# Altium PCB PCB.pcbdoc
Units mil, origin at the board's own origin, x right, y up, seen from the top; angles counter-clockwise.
Board outline 2756 x 2755.7 mil, 2 copper layers (Top Layer, Bottom Layer), stack 62.2 mil thick; 25 components, 17 nets, 72 pads, 16 vias.
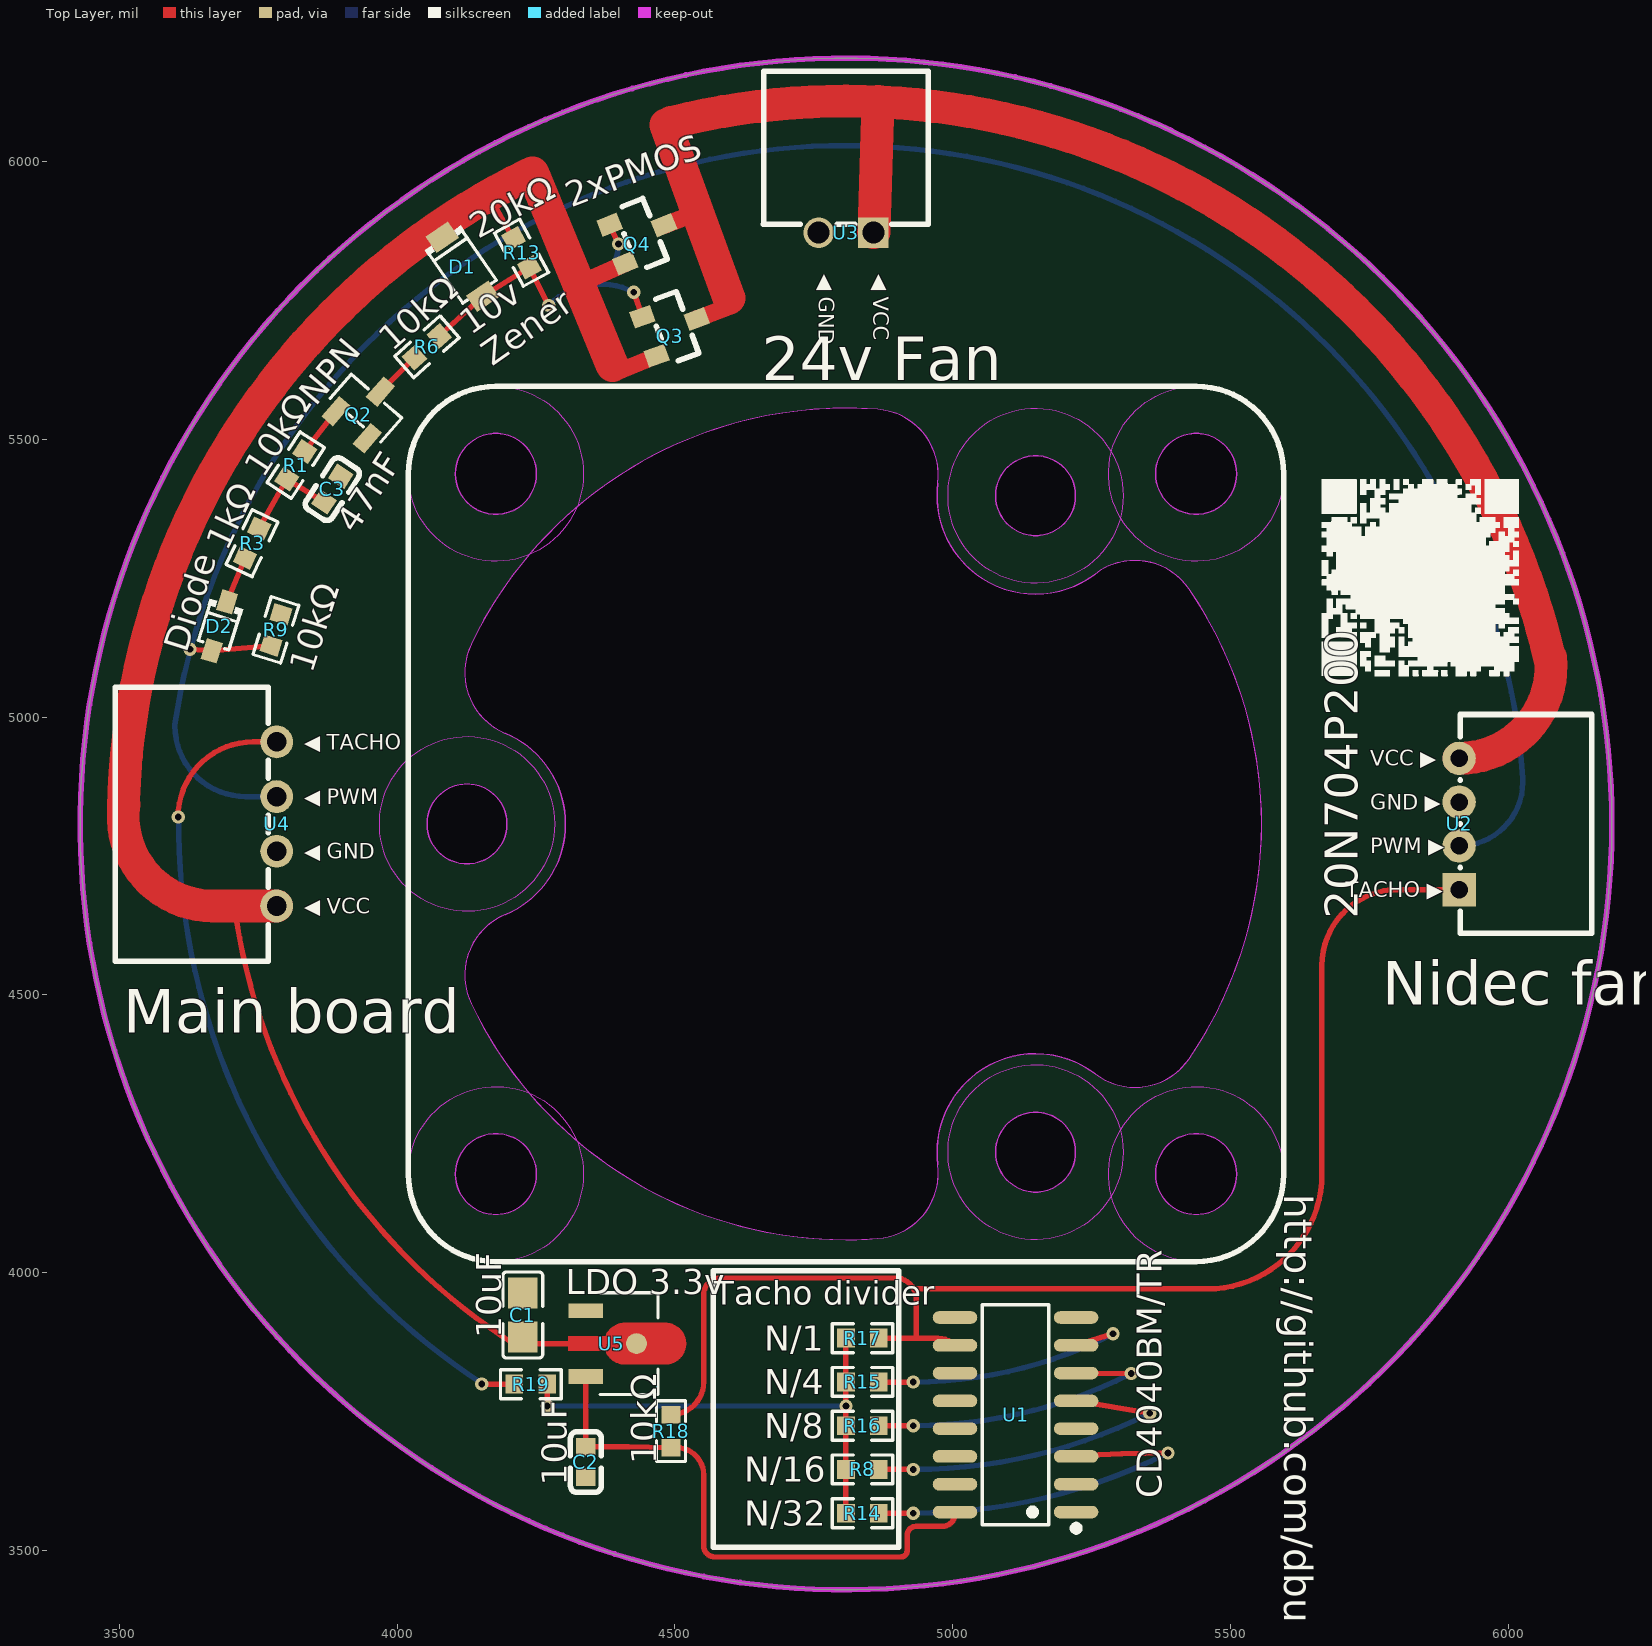
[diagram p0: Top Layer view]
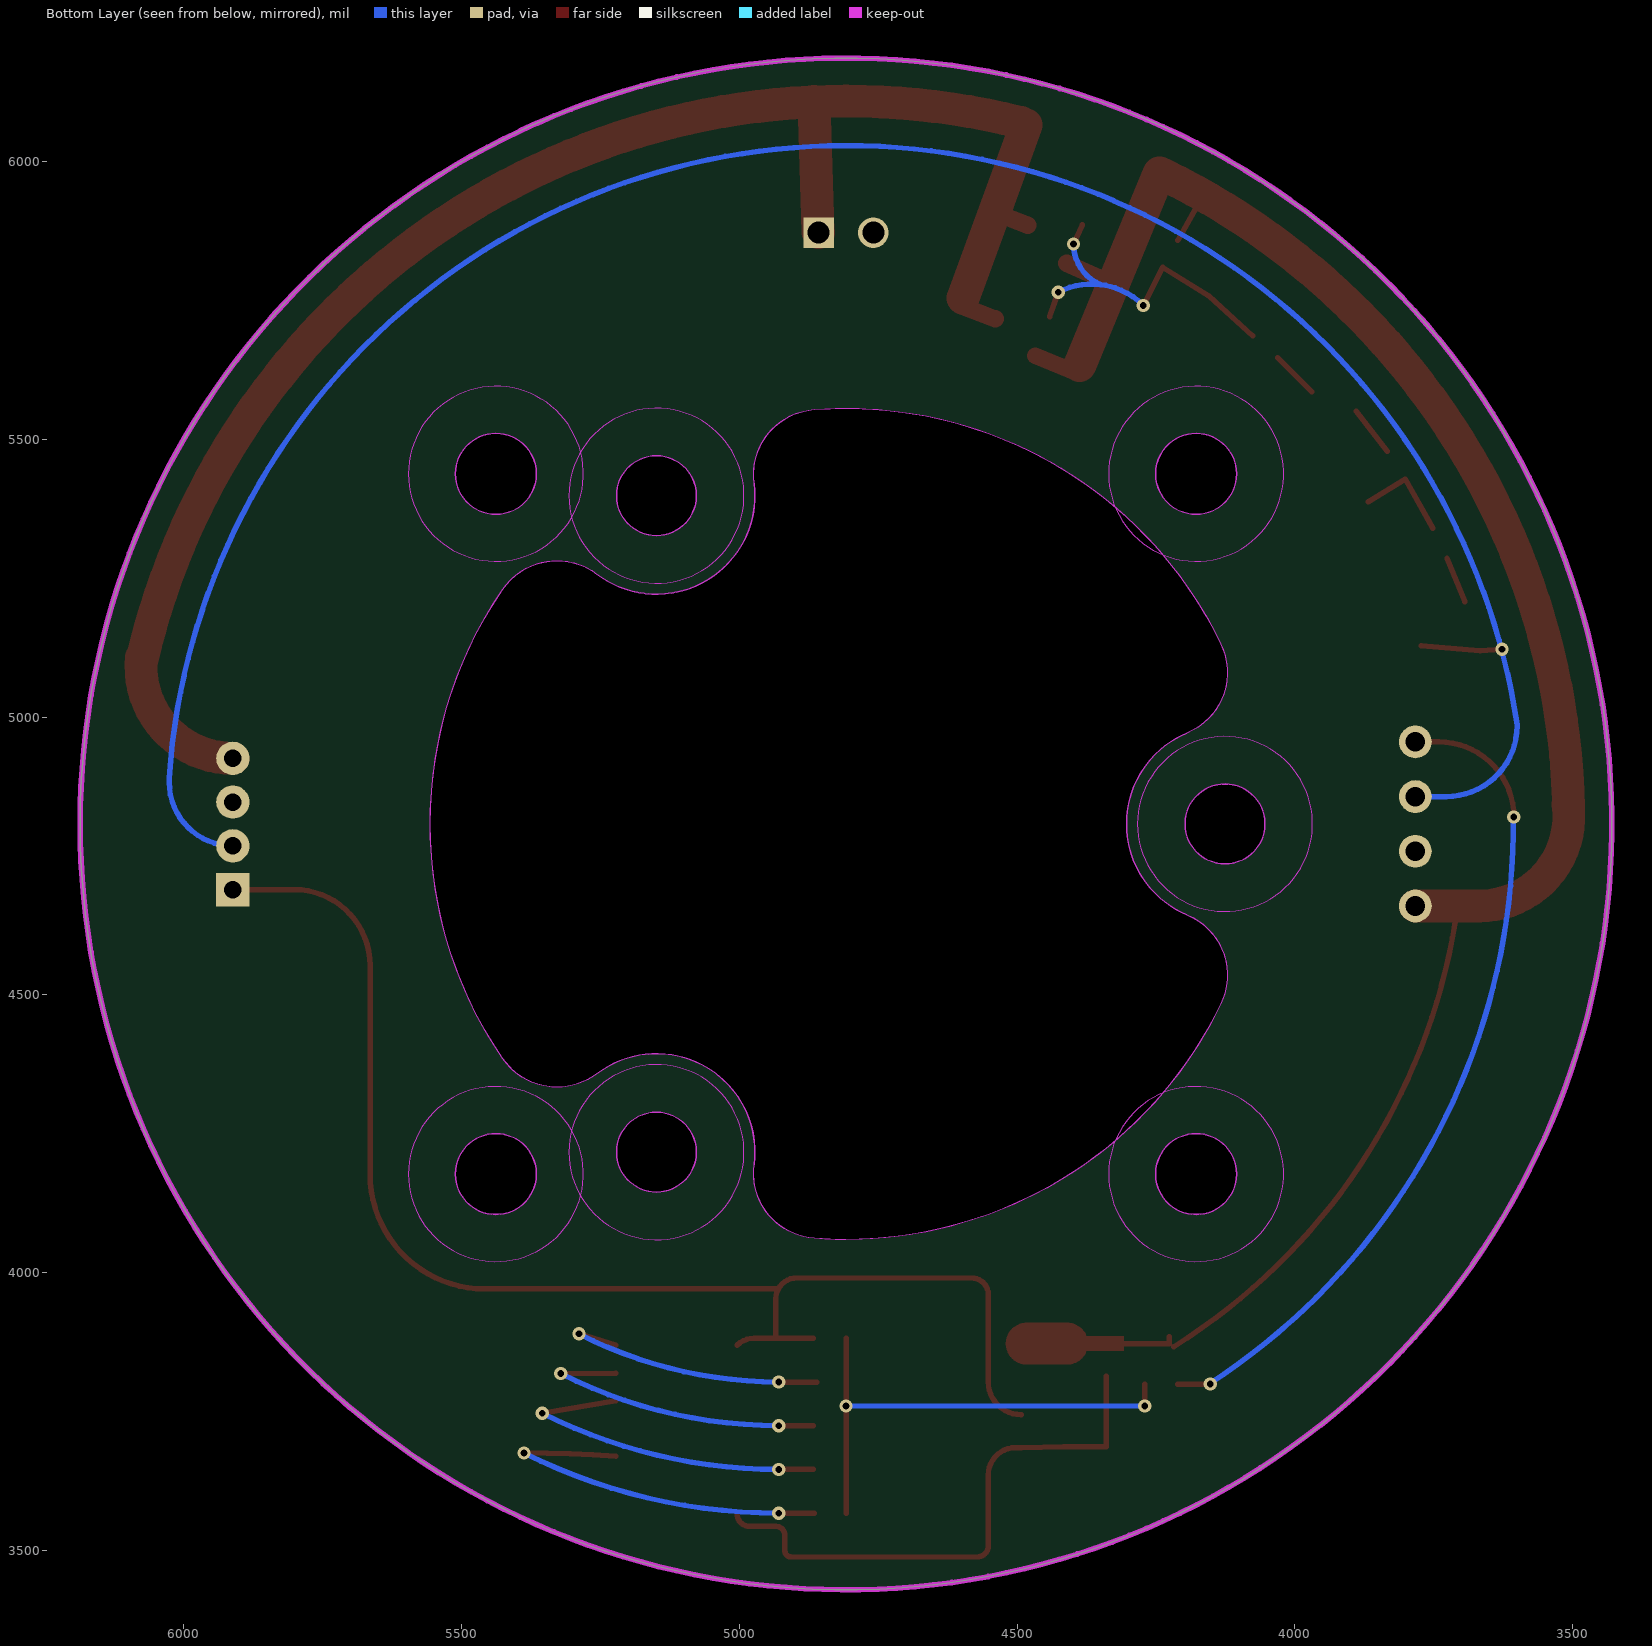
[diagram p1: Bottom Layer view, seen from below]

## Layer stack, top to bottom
Top Solder Mask Layer: solder mask 0.4, Dk 3.3
Top Layer: signal copper 1.4
Dielectric1: surface 59.4, FR4, Dk 4.5
Bottom Layer: signal copper 1.4
Bottom Solder Mask Layer: solder mask 0.4, Dk 3.3

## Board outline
6185.7,4807.7 ccw(c4807.7,4807.7) 3429.8,4807.7 ccw(c4807.7,4807.7)
cut-out: 348 vertices, not listed, extent 4121.7,4059.7 5555.7,5555.7
cut-out: 5364.7,5437.6 5365.1,5445.3 5366.3,5452.8 5368.3,5460.2 5371,5467.3 5374.5,5474.1 5378.6,5480.5 5383.4,5486.4 5388.8,5491.8 5394.8,5496.6 5401.2,5500.8 5408,5504.2 5415.1,5507 5422.5,5508.9 5430,5510.1 5437.6,5510.5 5445.3,5510.1 5452.8,5508.9 5460.2,5507 5467.3,5504.2 5474.1,5500.8 5480.5,5496.6 5486.4,5491.8 5491.8,5486.4 5496.6,5480.5 5500.8,5474.1 5504.2,5467.3 5507,5460.2 5508.9,5452.8 5510.1,5445.3 5510.5,5437.6 5510.1,5430 5508.9,5422.5 5507,5415.1 5504.2,5408 5500.8,5401.2 5496.6,5394.8 5491.8,5388.8 5486.4,5383.4 5480.5,5378.6 5474.1,5374.5 5467.3,5371 5460.2,5368.3 5452.8,5366.3 5445.3,5365.1 5437.6,5364.7 5430,5365.1 5422.5,5366.3 5415.1,5368.3 5408,5371 5401.2,5374.5 5394.8,5378.6 5388.8,5383.4 5383.4,5388.8 5378.6,5394.8 5374.5,5401.2 5371,5408 5368.3,5415.1 5366.3,5422.5 5365.1,5430
cut-out: 5364.7,4177.8 5365.1,4185.4 5366.3,4192.9 5368.3,4200.3 5371,4207.4 5374.5,4214.2 5378.6,4220.6 5383.4,4226.6 5388.8,4232 5394.8,4236.8 5401.2,4240.9 5408,4244.4 5415.1,4247.1 5422.5,4249.1 5430,4250.3 5437.6,4250.7 5445.3,4250.3 5452.8,4249.1 5460.2,4247.1 5467.3,4244.4 5474.1,4240.9 5480.5,4236.8 5486.4,4232 5491.8,4226.6 5496.6,4220.6 5500.8,4214.2 5504.2,4207.4 5507,4200.3 5508.9,4192.9 5510.1,4185.4 5510.5,4177.8 5510.1,4170.2 5508.9,4162.6 5507,4155.3 5504.2,4148.1 5500.8,4141.3 5496.6,4134.9 5491.8,4129 5486.4,4123.6 5480.5,4118.8 5474.1,4114.6 5467.3,4111.2 5460.2,4108.4 5452.8,4106.5 5445.3,4105.3 5437.6,4104.9 5430,4105.3 5422.5,4106.5 5415.1,4108.4 5408,4111.2 5401.2,4114.6 5394.8,4118.8 5388.8,4123.6 5383.4,4129 5378.6,4134.9 5374.5,4141.3 5371,4148.1 5368.3,4155.3 5366.3,4162.6 5365.1,4170.2
cut-out: 5076.7,4217.2 5077.1,4224.7 5078.3,4232.1 5080.3,4239.4 5083,4246.4 5086.4,4253.1 5090.5,4259.4 5095.2,4265.3 5100.5,4270.6 5106.4,4275.4 5112.7,4279.5 5119.4,4282.9 5126.4,4285.6 5133.7,4287.5 5141.1,4288.7 5148.7,4289.1 5156.2,4288.7 5163.6,4287.5 5170.9,4285.6 5177.9,4282.9 5184.6,4279.5 5190.9,4275.4 5196.8,4270.6 5202.1,4265.3 5206.9,4259.4 5211,4253.1 5214.4,4246.4 5217.1,4239.4 5219,4232.1 5220.2,4224.7 5220.6,4217.2 5220.2,4209.6 5219,4202.2 5217.1,4194.9 5214.4,4187.9 5211,4181.2 5206.9,4174.9 5202.1,4169 5196.8,4163.7 5190.9,4159 5184.6,4154.9 5177.9,4151.4 5170.9,4148.8 5163.6,4146.8 5156.2,4145.6 5148.7,4145.2 5141.1,4145.6 5133.7,4146.8 5126.4,4148.8 5119.4,4151.4 5112.7,4154.9 5106.4,4159 5100.5,4163.7 5095.2,4169 5090.5,4174.9 5086.4,4181.2 5083,4187.9 5080.3,4194.9 5078.3,4202.2 5077.1,4209.6
cut-out: 5076.7,5398.3 5077.1,5405.8 5078.3,5413.2 5080.3,5420.5 5083,5427.5 5086.4,5434.2 5090.5,5440.5 5095.2,5446.4 5100.5,5451.7 5106.4,5456.5 5112.7,5460.6 5119.4,5464 5126.4,5466.7 5133.7,5468.6 5141.1,5469.8 5148.7,5470.2 5156.2,5469.8 5163.6,5468.6 5170.9,5466.7 5177.9,5464 5184.6,5460.6 5190.9,5456.5 5196.8,5451.7 5202.1,5446.4 5206.9,5440.5 5211,5434.2 5214.4,5427.5 5217.1,5420.5 5219,5413.2 5220.2,5405.8 5220.6,5398.3 5220.2,5390.7 5219,5383.3 5217.1,5376 5214.4,5369 5211,5362.3 5206.9,5356 5202.1,5350.1 5196.8,5344.8 5190.9,5340.1 5184.6,5336 5177.9,5332.5 5170.9,5329.9 5163.6,5327.9 5156.2,5326.7 5148.7,5326.3 5141.1,5326.7 5133.7,5327.9 5126.4,5329.9 5119.4,5332.5 5112.7,5336 5106.4,5340.1 5100.5,5344.8 5095.2,5350.1 5090.5,5356 5086.4,5362.3 5083,5369 5080.3,5376 5078.3,5383.3 5077.1,5390.7
cut-out: 4104.9,5437.6 4105.3,5445.3 4106.5,5452.8 4108.4,5460.2 4111.2,5467.3 4114.6,5474.1 4118.8,5480.5 4123.6,5486.4 4129,5491.8 4134.9,5496.6 4141.3,5500.8 4148.1,5504.2 4155.3,5507 4162.6,5508.9 4170.2,5510.1 4177.8,5510.5 4185.4,5510.1 4192.9,5508.9 4200.3,5507 4207.4,5504.2 4214.2,5500.8 4220.6,5496.6 4226.6,5491.8 4232,5486.4 4236.8,5480.5 4240.9,5474.1 4244.4,5467.3 4247.1,5460.2 4249.1,5452.8 4250.3,5445.3 4250.7,5437.6 4250.3,5430 4249.1,5422.5 4247.1,5415.1 4244.4,5408 4240.9,5401.2 4236.8,5394.8 4232,5388.8 4226.6,5383.4 4220.6,5378.6 4214.2,5374.5 4207.4,5371 4200.3,5368.3 4192.9,5366.3 4185.4,5365.1 4177.8,5364.7 4170.2,5365.1 4162.6,5366.3 4155.3,5368.3 4148.1,5371 4141.3,5374.5 4134.9,5378.6 4129,5383.4 4123.6,5388.8 4118.8,5394.8 4114.6,5401.2 4111.2,5408 4108.4,5415.1 4106.5,5422.5 4105.3,5430
cut-out: 4053.9,4807.7 4054.3,4815.2 4055.4,4822.7 4057.4,4829.9 4060.1,4837 4063.5,4843.7 4067.6,4850 4072.3,4855.8 4077.7,4861.2 4083.5,4865.9 4089.8,4870 4096.5,4873.4 4103.6,4876.1 4110.8,4878.1 4118.3,4879.2 4125.8,4879.6 4133.3,4879.2 4140.8,4878.1 4148,4876.1 4155.1,4873.4 4161.8,4870 4168.1,4865.9 4173.9,4861.2 4179.3,4855.8 4184,4850 4188.1,4843.7 4191.5,4837 4194.2,4829.9 4196.2,4822.7 4197.3,4815.2 4197.7,4807.7 4197.3,4800.2 4196.2,4792.8 4194.2,4785.5 4191.5,4778.5 4188.1,4771.7 4184,4765.4 4179.3,4759.6 4173.9,4754.3 4168.1,4749.5 4161.8,4745.4 4155.1,4742 4148,4739.3 4140.8,4737.4 4133.3,4736.2 4125.8,4735.8 4118.3,4736.2 4110.8,4737.4 4103.6,4739.3 4096.5,4742 4089.8,4745.4 4083.5,4749.5 4077.7,4754.3 4072.3,4759.6 4067.6,4765.4 4063.5,4771.7 4060.1,4778.5 4057.4,4785.5 4055.4,4792.8 4054.3,4800.2
cut-out: 4104.9,4177.8 4105.3,4185.4 4106.5,4192.9 4108.4,4200.3 4111.2,4207.4 4114.6,4214.2 4118.8,4220.6 4123.6,4226.6 4129,4232 4134.9,4236.8 4141.3,4240.9 4148.1,4244.4 4155.3,4247.1 4162.6,4249.1 4170.2,4250.3 4177.8,4250.7 4185.4,4250.3 4192.9,4249.1 4200.3,4247.1 4207.4,4244.4 4214.2,4240.9 4220.6,4236.8 4226.6,4232 4232,4226.6 4236.8,4220.6 4240.9,4214.2 4244.4,4207.4 4247.1,4200.3 4249.1,4192.9 4250.3,4185.4 4250.7,4177.8 4250.3,4170.2 4249.1,4162.6 4247.1,4155.3 4244.4,4148.1 4240.9,4141.3 4236.8,4134.9 4232,4129 4226.6,4123.6 4220.6,4118.8 4214.2,4114.6 4207.4,4111.2 4200.3,4108.4 4192.9,4106.5 4185.4,4105.3 4177.8,4104.9 4170.2,4105.3 4162.6,4106.5 4155.3,4108.4 4148.1,4111.2 4141.3,4114.6 4134.9,4118.8 4129,4123.6 4123.6,4129 4118.8,4134.9 4114.6,4141.3 4111.2,4148.1 4108.4,4155.3 4106.5,4162.6 4105.3,4170.2

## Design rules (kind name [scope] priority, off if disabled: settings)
BoardOutlineClearance safeClearance [All] p0: genericclearance=10 ignorepadtopadclearanceinfootprint=FALSE except(0: Arc-SplitContinuation Track-SplitContinuation SMDPad-SplitContinuation THPad-SplitContinuation Via-SplitContinuation Fill-SplitContinuation Poly-SplitContinuation Region-SplitContinuation Text-SplitContinuation)
BoardOutlineClearance Plane_innerPlane [All] p0: genericclearance=10 ignorepadtopadclearanceinfootprint=FALSE except(0: Arc-SplitContinuation Track-SplitContinuation SMDPad-SplitContinuation THPad-SplitContinuation Via-SplitContinuation Fill-SplitContinuation Poly-SplitContinuation Region-SplitContinuation Text-SplitContinuation)
BoardOutlineClearance Copper_copperRegion [All] p0: genericclearance=10 ignorepadtopadclearanceinfootprint=FALSE except(0: Arc-SplitContinuation Track-SplitContinuation SMDPad-SplitContinuation THPad-SplitContinuation Via-SplitContinuation Fill-SplitContinuation Poly-SplitContinuation Region-SplitContinuation Text-SplitContinuation)
BoardOutlineClearance thick [All] p0: genericclearance=10 ignorepadtopadclearanceinfootprint=FALSE except(0: Arc-SplitContinuation Track-SplitContinuation SMDPad-SplitContinuation THPad-SplitContinuation Via-SplitContinuation Fill-SplitContinuation Poly-SplitContinuation Region-SplitContinuation Text-SplitContinuation)
BoardOutlineClearance gge47079 [All] p0: genericclearance=10 ignorepadtopadclearanceinfootprint=FALSE except(0: Arc-SplitContinuation Track-SplitContinuation SMDPad-SplitContinuation THPad-SplitContinuation Via-SplitContinuation Fill-SplitContinuation Poly-SplitContinuation Region-SplitContinuation Text-SplitContinuation)
BoardOutlineClearance gge47079(1) [All] p0: genericclearance=10 ignorepadtopadclearanceinfootprint=FALSE except(0: Arc-SplitContinuation Track-SplitContinuation SMDPad-SplitContinuation THPad-SplitContinuation Via-SplitContinuation Fill-SplitContinuation Poly-SplitContinuation Region-SplitContinuation Text-SplitContinuation)
BoardOutlineClearance Common [All] p0: genericclearance=10 ignorepadtopadclearanceinfootprint=FALSE except(0: Arc-SplitContinuation Track-SplitContinuation SMDPad-SplitContinuation THPad-SplitContinuation Via-SplitContinuation Fill-SplitContinuation Poly-SplitContinuation Region-SplitContinuation Text-SplitContinuation)
Clearance safeClearance [All] p1: gap=7 ignorepadtopadclearanceinfootprint=FALSE
Clearance Plane_innerPlane [All] p1: gap=7 ignorepadtopadclearanceinfootprint=FALSE
Clearance Copper_copperRegion [All] p1: gap=7 ignorepadtopadclearanceinfootprint=FALSE
Clearance thick [All] p1: gap=7 ignorepadtopadclearanceinfootprint=FALSE
Clearance gge47079 [All] p1: gap=7 ignorepadtopadclearanceinfootprint=FALSE
Clearance gge47079(1) [All] p1: gap=7 ignorepadtopadclearanceinfootprint=FALSE
Clearance Common [All] p1: gap=7 ignorepadtopadclearanceinfootprint=FALSE
DiffPairsRouting differentialPair [All] p1: maxuncoupledlength=10 minlimit=6 maxlimit=Infinity mostfreqgap=6 toplayer_minwidth=5 toplayer_prefwidth=10 toplayer_maxwidth=100 bottomlayer_minwidth=5 bottomlayer_prefwidth=10 bottomlayer_maxwidth=100
PasteMaskExpansion pasteMaskExpansion [All] p1: expansion=0
PlaneConnect innerPlane [All] p1: planeconnectstyle=Relief reliefexpansion=20 reliefentries=4 reliefconductorwidth=10 reliefairgap=10
PolygonConnect copperRegion [All] p1: connectstyle=Direct reliefentries=4 reliefconductorwidth=10 polygonreliefangle="90 Angle" airgapwidth=10
RoutingVias viaSize [All] p1: viastyle="Through Hole" holewidth=12 minholewidth=11.8 maxholewidth=236.2 width=12 minwidth=11.8 maxwidth=236.2
SolderMaskExpansion solderMaskExpansion [IsVia] p1: useseparateexpansions=TRUE expansion=-1000 expansionbottom=-1000
SolderMaskExpansion solderMaskExpansion [All] p2: useseparateexpansions=TRUE expansion=2 expansionbottom=2
Width trackWidth [All] p1: maxlimit=100 minlimit=5 preferedwidth=10

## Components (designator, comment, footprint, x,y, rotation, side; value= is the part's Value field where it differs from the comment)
C1 "10uF" C0805 4226.3,3924.2 r90 top
C2 "10uF" C0603#1 4339.7,3659.7 r270 top
C3 "47nF" C0603#2 3883.6,5410.2 r236.9 top
D1 "MMSZ5240B" SOD-123_L2.7-W1.6-LS3.7-RD 4117.7,5810 r304.4 top
D2 "1N5819WS" SOD-323_L1.8-W1.3-LS2.5-RD 3680.4,5163.1 r252.5 top
Q2 "SS8050(RANGE:200-350)" SOT-23-3_L2.9-W1.3-P1.90-LS2.4-BR 3944.1,5555.8 r229.1 top
Q3 "AO3401A" SOT-23_L2.9-W1.3-P1.90-LS2.4-BR#1 4496.7,5700.7 r200 top
Q4 "AO3401A" SOT-23_L2.9-W1.3-P1.90-LS2.4-BR#2 4438.4,5868.1 r202.1 top
R1 "10kΩ" R0603#1 3817.6,5453.2 r56.9 top
R3 "1kΩ" R0603#2 3739.1,5312.8 r64.7 top
R6 "10kΩ" R0603#3 4053.6,5666.1 r41.4 top
R8 "N/16" R0603#4 4837.2,3646.3 r0 top
R9 "10kΩ" R0603#5 3782,5156.9 r252.3 top
R13 "20kΩ" R0603#6 4223.9,5835.4 r118.6 top
R14 "N/32" R0603#4 4837.2,3567.6 r0 top
R15 "N/4" R0603#4 4837.2,3803.8 r0 top
R16 "N/8" R0603#7 4837.2,3725 r180 top
R17 "N/1" R0603#7 4837.2,3882.5 r180 top
R18 "10kΩ" R0603#4 4492.7,3715.2 r270 top
R19 "1kΩ" R0603#4 4240.8,3799.8 r180 top
U1 "CD4040BM/TR" SOP-16_L9.9-W3.9-P1.27-LS6.0-BL 5112.8,3744.7 r90 top
U2 "JS20T-S04PHW-00" CONN-TH_4P-P2.00_JS20T-S04PHW-00 5910.9,4807.7 r90 top
U3 "XY-XH2.54-2A21" HDR-TH_2P-P2.50_XY-XH2.54-2A21 4807.7,5871.5 r180 top
U4 "XY-XH2.54-4A21" HDR-TH_4P-P2.50-H-F-W7.0-N 3783.3,4807.7 r270 top
U5 "HT7533-1" SOT-89-3_L4.5-W2.5-P1.50-LS4.2-BR 4392.8,3872.8 r180 top

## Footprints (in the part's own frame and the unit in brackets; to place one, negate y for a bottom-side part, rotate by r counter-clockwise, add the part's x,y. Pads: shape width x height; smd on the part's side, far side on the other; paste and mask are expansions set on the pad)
C0603#1 [mil]
  rect 31.5x35.4 smd: 1(-27.6,0) 2(27.6,0)
  silkscreen extent -55,-28 55,28
C0603#2 [mil]
  rect 31.5x35.4 smd: 1(-27.46,0.01) 2(27.6,-0.03)
  silkscreen extent -55,-28 55,28
C0805 [mil]
  rect 55.5x53.1 smd paste-3937 mask+2: 1(-39.4,0) 2(39.3,0)
  silkscreen extent -77,-36 77,36
CONN-TH_4P-P2.00_JS20T-S04PHW-00 [mil]
  rect 60x60 hole 31.5: 1(-118.1,0)
  round 60 hole 31.5: 2(-39.4,0) 3(39.4,0) 4(118.1,0)
  silkscreen extent -197,-238 197,-2
HDR-TH_2P-P2.50_XY-XH2.54-2A21 [mil]
  rect 55.1x55.1 hole 39.4 paste+0 mask+2: 1(-49.2,0)
  round 55.1 hole 39.4 paste+0 mask+2: 2(49.2,0)
  silkscreen extent -148,-291 149,-15
HDR-TH_4P-P2.50-H-F-W7.0-N [mil]
  round 59.1 hole 35.4 paste+0 mask+2: 1(-147.7,0) 2(-49.2,0) 3(49.2,0) 4(147.6,0)
  silkscreen extent -246,-291 247,-15
R0603#1 [mil]
  rect 31.8x34 smd paste-3937 mask+2: 1(-29.71,-0.03) 2(29.57,0.06)
  silkscreen extent -55,-26 55,26
R0603#2 [mil]
  rect 31.8x34 smd paste-3937 mask+2: 1(-29.66,0.03) 2(29.66,-0.03)
  silkscreen extent -55,-26 55,26
R0603#3 [mil]
  rect 31.8x34 smd rot 0.01 paste-3937 mask+2: 1(-29.61,-0.02) 2(29.69,-0.05)
  silkscreen extent -55,-26 55,26
R0603#4 [mil]
  rect 31.8x34 smd paste-3937 mask+2: 1(-29.6,0) 2(29.7,0)
  silkscreen extent -54,-26 55,26
R0603#5 [mil]
  rect 31.8x34 smd rot 0.03 paste-3937 mask+2: 1(-29.6,0) 2(29.7,0.03)
  silkscreen extent -55,-26 55,26
R0603#6 [mil]
  rect 31.8x34 smd rot 179.98 paste-3937 mask+2: 1(-29.62,-0.02) 2(29.71,-0.03)
  silkscreen extent -54,-26 55,26
R0603#7 [mil]
  rect 31.8x34 smd paste-3937 mask+2: 1(-29.7,0) 2(29.6,0)
  silkscreen extent -55,-26 54,26
SOD-123_L2.7-W1.6-LS3.7-RD [mil]
  rect 35.8x48 smd rot 0.04: 1(-64.38,-0.03) 2(64.3,0.09)
  silkscreen extent -63,-40 54,39
SOD-323_L1.8-W1.3-LS2.5-RD [mil]
  rect 39.4x29.5 smd: 1(-46.24,0) 2(46.11,0.07)
  silkscreen extent -43,-32 35,32
SOP-16_L9.9-W3.9-P1.27-LS6.0-BL [mil]
  oval 22.6x80.2 smd: 1(-175,-109) 2(-125,-109) 3(-75,-109) 4(-25,-109) 5(25,-109) 6(75,-109) 7(125,-109) 8(175,-109) 9(175,109) 10(125,109) 11(75,109) 12(25,109) 13(-25,109) 14(-75,109) 15(-125,109) 16(-175,109)
  silkscreen extent -210,-115 198,60
SOT-23-3_L2.9-W1.3-P1.90-LS2.4-BR [mil]
  rect 49.2x27.6 smd: 1(39.43,-37.42) 2(39.33,37.38) 3(-39.42,-0.01)
  silkscreen extent -29,-60 29,60
SOT-23_L2.9-W1.3-P1.90-LS2.4-BR#1 [mil]
  rect 39.4x31.5 smd: 1(45.26,-37.33) 2(45.22,37.39) 3(-45.33,0)
  silkscreen extent -28,-59 28,59
SOT-23_L2.9-W1.3-P1.90-LS2.4-BR#2 [mil]
  rect 39.4x31.5 smd rot 179.97: 1(45.23,-37.47) 2(45.3,37.4) 3(-45.31,0.05)
  silkscreen extent -28,-59 28,59
SOT-89-3_L4.5-W2.5-P1.50-LS4.2-BR [mil]
  rect 62x26.5 smd: 1(53.4,-59) 3(53.4,59.1)
  round 37.4 smd: 2(-38,0)
  Top Layer region: -89.9,37.4 -16.9,37.4 -15.1,37.4 -13.4,37.3 -11.6,37.1 -9.9,36.8 -8.2,36.4 -6.5,36 -4.8,35.4 -3.2,34.8 -1.6,34.2 0,33.4 1.6,32.6 3.1,31.7 4.5,30.7 6,29.7 7.3,28.6 8.6,27.4 9.9,26.2 11.1,24.9 12.2,23.6 13.3,22.2 14.3,20.7 15.2,19.2 16.1,17.7 16.9,16.2 17.6,13 84.4,13 84.4,-13 17.6,-13 16.9,-16.1 16.1,-17.6 15.2,-19.2 14.3,-20.6 13.3,-22.1 12.2,-23.5 11.1,-24.8 9.9,-26.1 8.6,-27.3 7.3,-28.5 6,-29.6 4.5,-30.6 3.1,-31.6 1.6,-32.5 0,-33.3 -1.6,-34.1 -3.2,-34.8 -4.8,-35.4 -6.5,-35.9 -8.2,-36.3 -9.9,-36.7 -11.6,-37 -13.4,-37.2 -15.1,-37.3 -16.9,-37.4 -89.9,-37.4 -91.6,-37.3 -93.4,-37.2 -95.1,-37 -96.8,-36.7 -98.6,-36.3 -100.3,-35.9 -101.9,-35.4 -103.6,-34.8 -105.2,-34.1 -106.8,-33.3 -108.3,-32.5 -109.8,-31.6 -111.3,-30.6 -112.7,-29.6 -114.1,-28.5 -115.4,-27.3 -116.6,-26.1 -117.8,-24.8 -119,-23.5 -120,-22.1 -121,-20.6 -122,-19.2 -122.8,-17.6 -123.6,-16.1 -124.3,-14.5 -125,-12.8 -125.5,-11.2 -126,-9.5 -126.4,-7.8 -126.8,-6.1 -127,-4.3 -127.2,-2.6 -127.3,-0.8 -127.3,0.9 -127.2,2.7 -127,4.4 -126.8,6.1 -126.4,7.9 -126,9.6 -125.5,11.3 -125,12.9 -124.3,14.6 -123.6,16.2 -122.8,17.7 -122,19.2 -121,20.7 -120,22.2 -119,23.6 -117.8,24.9 -116.6,26.2 -115.4,27.4 -114.1,28.6 -112.7,29.7 -111.3,30.7 -109.8,31.7 -108.3,32.6 -106.8,33.4 -105.2,34.2 -103.6,34.8 -101.9,35.4 -100.3,36 -98.6,36.4 -96.8,36.8 -95.1,37.1 -93.4,37.3 -91.6,37.4
  silkscreen extent -77,-92 28,92

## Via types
v1: diameter 24, hole 12, Top Layer to Bottom Layer, 16 vias

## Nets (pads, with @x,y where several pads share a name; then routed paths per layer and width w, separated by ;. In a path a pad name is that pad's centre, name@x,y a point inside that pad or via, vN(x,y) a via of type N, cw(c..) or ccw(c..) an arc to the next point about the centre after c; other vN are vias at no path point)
3.3V: C2.1 R18.2 U1.16 U5.3 | length 1016.6
  Top Layer w9.8: U5.3 C2.1 ; C2.1@4339.7,3687.2 cw(c4339.7,-3044.9) R18.2@4492.43,3685.47 ; R18.2 4502.7,3685.5 cw(c4502.7,3636.4) 4551.8,3636.4 4551.8,3508.5 ccw(c4571.5,3508.5) 4571.5,3488.8 4906.1,3488.8 ccw(c4906.1,3500.6) 4917.9,3500.6 4917.9,3528.2 ; 4918,3528.2 cw(c4933.7,3528.2) 4933.7,3543.9 4980.9,3543.9 ccw(c4980.9,3566.8) 5003.8,3566.8 U1.16
$1N3: C3.2 R1.1 R3.2 | length 180.4
  Top Layer w9.8: R3.2 R1.1 C3.2
$1N2590: Q2.1 R1.2 | length 91.8
  Top Layer w9.8: R1.2 Q2.1
$1N6630: D2.1 R3.1 | length 85.1
  Top Layer w9.8: D2.1 R3.1
$1N7011: D1.2 Q3.1 Q4.1 R6.2 R13.1 | length 626
  Top Layer w9.8: R6.2 D1.2 R13.1 v1(4272.8,5740.4) ; Q4.1 v1(4398.3,5851) ; v1(4425.8,5764.4) Q3.1
  Bottom Layer w9.8: v1@4272.72,5740.48 cw(c4365.7,5647.5) 4323.54,5772.06 cw(c4365.7,5647.5) 4349.45,5777.99 cw(c4365.7,5647.5) v1@4425.81,5764.46 ; 4349.37,5777.92 ccw(c4319.1,5851) v1@4398.2,5851
$1N7284: Q2.3 R6.1 | length 86.6
  Top Layer w9.8: Q2.3 R6.1
$1N9152: R15.2 U1.7 | length 511.2
  Top Layer w9.8: R15.2@4860.3,3803.4 4928,3803.4 v1(4928.4,3803.8) ; U1.7 v1(5288,3890.4)
  Bottom Layer w9.8: v1@4928.4,3803.7 ccw(c4928.4,4593.6) v1@5288.23,3890.42
$1N9209: R14.2 U1.3 | length 705.6
  Top Layer w9.8: R14.2@4864.5,3567.2 v1@4928.8,3567.2 ; U1.3@5221.55,3669.69 cw(c5387,1469.3) v1(5387,3675.9)
  Bottom Layer w9.8: v1@4928.4,3567.5 ccw(c4928.4,4592.2) v1@5387.22,3675.96
  other v1: 4928.4,3567.6
$1N9354: R8.1 R14.1 R15.1 R16.2 R17.2 R19.1 | length 891.5
  Top Layer w9.8: v1(4270.4,3760.5) R19.1 ; R14.1 R8.1 R16.2 R15.1 R17.2
  Bottom Layer w9.8: v1(4270.4,3760.5) v1(4807.7,3760.5)
$1N9370: R16.1 U1.6 | length 565.7
  Top Layer w9.8: R16.1 v1@4925.8,3725 ; U1.6 v1(5321,3818.9)
  Bottom Layer w9.8: v1(4928.4,3725) ccw(c4928.4,4593.1) v1@5321.16,3818.93
$1N9374: R8.2 U1.5 | length 629.2
  Top Layer w9.8: R8.2 v1@4921.1,3646.3 ; U1.5 v1(5354,3747.4)
  Bottom Layer w9.8: v1(4928.4,3646.3) ccw(c4928.4,4592.6) v1@5353.59,3747.2
GND: C1.2 C2.2 C3.1 Q2.2 R9.1 U1.8 U1.11 U2.3 U3.2 U4.3 U5.1
PWM: D2.2 R9.2 U2.2 U4.2 | length 4163.5
  Top Layer w9.8: v1(3627.4,5121.8) D2.2 R9.2
  Bottom Layer w9.8: 3600.2,4984.3 ccw(c3727.6,4984.3) 3727.6,4856.9 U4.2 ; 3600.3,4986 3605.3,5016.7 3611,5047.2 3617.4,5077.6 3624.7,5107.8 3632.7,5137.8 3641.5,5167.6 3651,5197.1 3661.3,5226.5 3672.4,5255.5 3684.1,5284.2 3696.6,5312.7 3709.8,5340.8 3723.7,5368.6 3738.4,5396 3753.7,5423 3769.7,5449.6 3786.3,5475.8 3803.7,5501.6 3821.7,5526.9 3840.3,5551.8 3859.5,5576.2 3879.4,5600 3899.9,5623.4 3920.9,5646.3 3942.5,5668.5 3964.7,5690.3 3987.5,5711.5 4010.7,5732 4034.5,5752 4058.8,5771.4 4083.6,5790.1 4108.8,5808.2 4134.5,5825.7 4160.6,5842.5 4187.2,5858.6 4214.1,5874.1 4241.4,5888.9 4269.1,5902.9 4297.2,5916.3 4325.6,5928.9 4354.2,5940.8 4383.2,5952 4412.5,5962.4 4442,5972.1 4471.7,5981 4501.7,5989.2 4531.9,5996.6 4562.2,6003.2 4592.7,6009.1 4623.4,6014.2 4654.1,6018.5 4685,6022 4715.9,6024.7 4746.9,6026.7 4778,6027.8 4809,6028.2 4840.1,6027.8 4871.1,6026.5 4902.1,6024.5 4933.1,6021.7 4963.9,6018.1 4994.7,6013.8 5025.3,6008.6 5055.8,6002.7 5086.1,5996 5116.3,5988.5 5146.2,5980.3 5176,5971.3 5205.5,5961.5 5234.7,5951.1 5263.7,5939.8 5292.3,5927.8 5320.7,5915.2 5348.7,5901.7 5376.3,5887.6 5403.6,5872.8 5430.6,5857.3 5457.1,5841.1 5483.2,5824.2 5508.8,5806.7 5534,5788.6 5558.7,5769.8 5583,5750.3 5606.7,5730.3 5629.9,5709.7 5652.6,5688.4 5674.8,5666.7 5696.3,5644.3 5717.3,5621.4 5737.7,5598 5757.6,5574.1 5776.8,5549.7 5795.3,5524.8 5813.2,5499.4 5830.5,5473.6 5847.1,5447.3 5863.1,5420.7 5878.3,5393.6 5892.9,5366.2 5906.8,5338.4 5919.9,5310.3 5932.3,5281.8 5944,5253 5955,5224 5965.2,5194.6 5974.7,5165 5983.4,5135.2 5991.4,5105.2 5998.6,5075 6005,5044.6 6010.6,5014 6015.5,4983.4 6019.6,4952.6 6022.8,4921.7 6025.4,4890.7 ; U2.2 ccw(c5910.9,4882.7) 6025.3,4882.7 6025.3,4892.4
TACHO: R17.1 R18.1 U1.10 U2.1 | length 2434.4
  Top Layer w9.8: R18.1 ccw(c4492.7,3803.9) 4551.8,3803.9 4551.8,3961.3 cw(c4581.3,3961.3) 4581.3,3990.8 4896.3,3990.8 cw(c4896.3,3952.9) 4929.54,3971.1 cw(c4896.3,3952.9) 4934.2,3952.9 ; R17.1 4934.1,3882.5 ; 4929.5,3971.1 5457.3,3971.1 ccw(c5457.3,4177.8) 5664,4177.8 5664,4553 cw(c5800.6,4553) 5800.6,4689.6 U2.1 ; 4934.1,3952.9 4934.1,3882.5 ; U1.10 ccw(c4972.9,3838.8) 4972.9,3882.5 4934.1,3882.5
TACHOBOARD: R19.2 U4.1 | length 1520.4
  Top Layer w9.8: v1(3606.1,4820.3) cw(c3741.2,4820.3) 3741.2,4955.4 ; 3741.2,4955.3 U4.1@3783.3,4955.3 ; v1(4152.3,3800) 4152.4,3799.8 R19.2
  Bottom Layer w9.8: v1@3607,4820.3 3607.1,4789.3 3607.9,4758.4 3609.6,4727.5 3612.1,4696.6 3615.3,4665.9 3619.4,4635.2 3624.2,4604.6 3629.9,4574.2 3636.3,4543.9 3643.5,4513.8 3651.4,4483.9 3660.1,4454.2 3669.6,4424.7 3679.9,4395.5 3690.9,4366.6 3702.6,4337.9 3715.1,4309.6 3728.3,4281.6 3742.2,4254 3756.9,4226.7 3772.2,4199.8 3788.2,4173.3 3804.9,4147.2 3822.2,4121.6 3840.2,4096.4 3858.9,4071.7 3878.2,4047.5 3898.1,4023.8 3918.6,4000.6 3939.7,3978 3961.4,3955.9 3983.6,3934.4 4006.4,3913.4 4029.7,3893.1 4053.5,3873.3 4077.9,3854.2 4102.7,3835.7 4128,3817.8 v1@4153.7,3800.6
VCC-IN: C1.1 D1.1 Q3.2 Q4.2 R13.2 U4.4 U5.2 | length 3649.9
  Top Layer w9.8: 3707.3,4660.9 3711.6,4631.7 3716.6,4602.6 3722.5,4573.7 3729.1,4544.9 3736.5,4516.3 3744.6,4487.9 3753.5,4459.7 3763.1,4431.8 3773.5,4404.1 3784.6,4376.8 3796.4,4349.7 3809,4323 3822.2,4296.6 3836.1,4270.5 3850.8,4244.9 3866.1,4219.6 3882.1,4194.8 3898.7,4170.4 3916,4146.4 3933.9,4122.9 3952.4,4099.9 3971.5,4077.4 3991.3,4055.5 4011.6,4034 4032.4,4013.1 4053.8,3992.8 4075.8,3973 4098.2,3953.8 4121.2,3935.2 4144.7,3917.3 4168.6,3900 4193,3883.3 C1.1@4217.8,3867.3 ; 4165.5,5938.2 R13.2@4210.6,5857.9 ; C1.1 4226.3,3872.8 U5.2@4446.2,3872.8
  Top Layer w29.5: 4390.9,5618.6 Q3.2
  Top Layer w31.5: 4337.9,5784 Q4.2
  Top Layer w59.1: 3507.4,4836.2 3508.5,4867.8 3510.3,4899.4 3512.9,4931 3516.3,4962.4 3520.5,4993.8 3525.4,5025.1 3531,5056.2 3537.5,5087.2 3544.6,5118 3552.6,5148.7 3561.2,5179.1 3570.6,5209.3 3580.8,5239.3 3591.6,5269 3603.2,5298.5 3615.5,5327.7 3628.5,5356.5 3642.2,5385 3656.6,5413.2 3671.7,5441.1 3687.5,5468.5 3703.9,5495.6 3720.9,5522.2 3738.6,5548.5 3757,5574.3 3776,5599.6 3795.5,5624.5 3815.7,5648.9 3836.5,5672.8 3857.8,5696.1 3879.7,5719 3902.2,5741.3 3925.1,5763.1 3948.6,5784.3 3972.7,5804.9 3997.2,5824.9 4022.2,5844.3 4047.6,5863.1 4073.5,5881.3 4099.9,5898.9 4126.6,5915.8 4153.8,5932 4181.3,5947.6 4209.3,5962.5 4237.5,5976.7 ; 3508.52,4843.2 ccw(c3668.9,4821.8) 3668.9,4660 ; 3668.9,4660.1 U4.4 ; 4243.9,5979.3 4387.4,5632.7
VCC-OUT: Q3.3 Q4.3 U2.4 U3.1 | length 3042.7
  Top Layer w31.5: Q4.3 4540.7,5908.1 ; Q3.3 4603.3,5741.1
  Top Layer w59.1: 4483.3,6065.3 4540.7,5908.1 4597,5753.8 ; 4493.1,6069.7 4524,6077 4555.1,6083.6 4586.3,6089.4 4617.7,6094.4 4649.2,6098.6 4680.8,6102.1 4712.5,6104.8 4744.2,6106.8 4775.9,6108 4807.7,6108.3 4839.5,6108 4871.2,6106.8 4903,6104.8 4934.6,6102.1 4966.2,6098.6 4997.7,6094.4 5029.1,6089.4 5060.3,6083.6 5091.4,6077 5122.4,6069.7 5153.1,6061.6 5183.6,6052.8 5213.9,6043.3 5244,6033 5273.8,6022 5303.3,6010.2 5332.6,5997.7 5361.5,5984.6 5390.1,5970.7 5418.3,5956.1 5446.2,5940.8 5473.7,5924.9 5500.8,5908.3 5527.5,5891 5553.7,5873.1 5579.5,5854.6 5604.9,5835.4 5629.7,5815.6 5654.1,5795.2 5678,5774.3 5701.4,5752.7 5724.2,5730.6 5746.5,5707.9 5768.2,5684.7 5789.3,5661 5809.9,5636.8 5829.8,5612 5849.2,5586.8 5867.9,5561.1 5886,5535 5903.4,5508.4 5920.2,5481.5 5936.4,5454.1 5951.8,5426.3 5966.6,5398.2 5980.7,5369.7 5994,5340.9 6006.7,5311.7 6018.7,5282.3 6029.9,5252.5 6040.4,5222.6 6050.2,5192.3 6059.2,5161.8 6067.5,5131.2 6075,5100.3 ; U3.1 4858,5872.5 4865.5,6107.6 ; U2.4 ccw(c5910.9,5091.1) 6075.44,5106.94
pads on no net: U1.1 U1.2 U1.4 U1.9 U1.12 U1.13 U1.14 U1.15

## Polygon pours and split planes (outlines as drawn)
GND on Bottom Layer (solid, remove dead copper, pour order 2): 300 vertices, not listed, extent 3000.1,3000 6615.4,6615.4
GND on Top Layer (solid, remove dead copper, pour order 0): 280 vertices, not listed, extent 3233,3232.9 6382.5,6382.5

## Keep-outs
Board Outline Layer:
  drawing of 320 lines, arcs and shapes, not listed

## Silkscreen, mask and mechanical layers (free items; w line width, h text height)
Top Silkscreen Layer:
  drawing of 33 lines, arcs and shapes, not listed
  text "2xPMOS" at 4313.6,5916.3 h45 r21
  text "◀ GND" at 4758.5,5796.9 h27.6 r270
  text "◀ VCC" at 4856.9,5796.9 h27.6 r270
  text "10v / Zener" at 4171.3,5630.4 h45 r35
  text "24v Fan" at 4656.3,5606.3 h78.7
  text "NPN" at 3853.7,5557.2 h45 r50
  text "Diode" at 3621.4,5114.3 h45 r72.5
  text "◀ TACHO" at 3833.3,4941.6 h27.6
  text "VCC ▶" at 5750.6,4912 h27.6
  text "◀ PWM" at 3833.3,4843.1 h27.6
  text "GND ▶" at 5750.6,4833.3 h27.6
  text "PWM ▶" at 5750.6,4754.6 h27.6
  text "◀ GND" at 3833.3,4744.7 h27.6
  text "TACHO ▶" at 5706.5,4675.8 h27.6
  text "◀ VCC" at 3833.3,4646.3 h27.6
  text "20N704P200" at 5728.2,4636.8 h59.1 r90
  text "Nidec fan" at 5772.6,4482.4 h78.7
  text "Main board" at 3507.1,4432.1 h78.7
  text "http://github.com/dbuezas/roborock-3d-printer-fan" at 5596.1,4141.4 h51.2 r270
  text "LDO 3.3v" at 4303.4,3961.7 h45
  text "Tacho divider" at 4570.3,3943 h42.9
Mechanical Layer:
  lines w0.1: 4133.13,4484.5 ccw(c4807.7,4807.7) 4807.7,4059.7 ; 4133.13,5130.9 cw(c4807.7,4807.7) 4807.7,5555.7 cw(c4807.7,4807.7) 4865.09,5553.5 ; 4133.19,4484.27 cw(c4239.7,4535.3) 4194.12,4644.25 ; 4133.19,5131.13 ccw(c4239.7,5080.1) 4194.12,4971.15 ; 4194.18,4644.23 ccw(c4125.8,4807.7) 4303,4807.7 ccw(c4125.8,4807.7) 4194.18,4971.17 ; 4864.86,4061.85 ccw(c4855.8,4179.6) 4972.94,4194.61 ; 4864.86,5553.55 cw(c4855.8,5435.8) 4972.94,5420.79 ccw(c5148.7,5398.3) 5256.08,5257.34 ; 4865.09,4061.9 cw(c4807.7,4807.7) 4807.7,4059.7 ; 4972.94,4194.68 cw(c5148.7,4217.2) 5256.08,4358.16 ; 5256.03,4358.05 ccw(c5327.6,4452) 5425.05,4385.28 ; 5256.03,5257.35 cw(c5327.6,5163.4) 5425.05,5230.12 ; 5424.88,4385.1 ccw(c4807.7,4807.7) 5555.7,4807.7 ccw(c4807.7,4807.7) 5424.88,5230.3 ; 4807.7,4059.7 4807.7,4059.7 ; 4053.9,4807.7 cw(c4125.8,4807.7) 4197.7,4807.7 cw(c4125.8,4807.7) 4053.9,4807.7 ; 4104.9,4177.8 cw(c4177.8,4177.8) 4250.7,4177.8 cw(c4177.8,4177.8) 4104.9,4177.8 ; 4104.9,5437.6 cw(c4177.8,5437.6) 4250.7,5437.6 cw(c4177.8,5437.6) 4104.9,5437.6 ; 4133.2,5131.2 4133.2,5131.2 ; 4864.8,4061.9 4864.8,4061.9 ; 5076.8,4217.2 cw(c5148.7,4217.2) 5220.6,4217.2 cw(c5148.7,4217.2) 5076.8,4217.2 ; 5076.8,5398.3 cw(c5148.7,5398.3) 5220.6,5398.3 cw(c5148.7,5398.3) 5076.8,5398.3 ; 5256,4358.1 5256,4358.1 ; 5256,5257.3 5256,5257.3 ; 5364.7,4177.8 cw(c5437.6,4177.8) 5510.5,4177.8 cw(c5437.6,4177.8) 5364.7,4177.8 ; 5364.7,5437.6 cw(c5437.6,5437.6) 5510.5,5437.6 cw(c5437.6,5437.6) 5364.7,5437.6 ; 5425.1,4385.3 5425.1,4385.3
